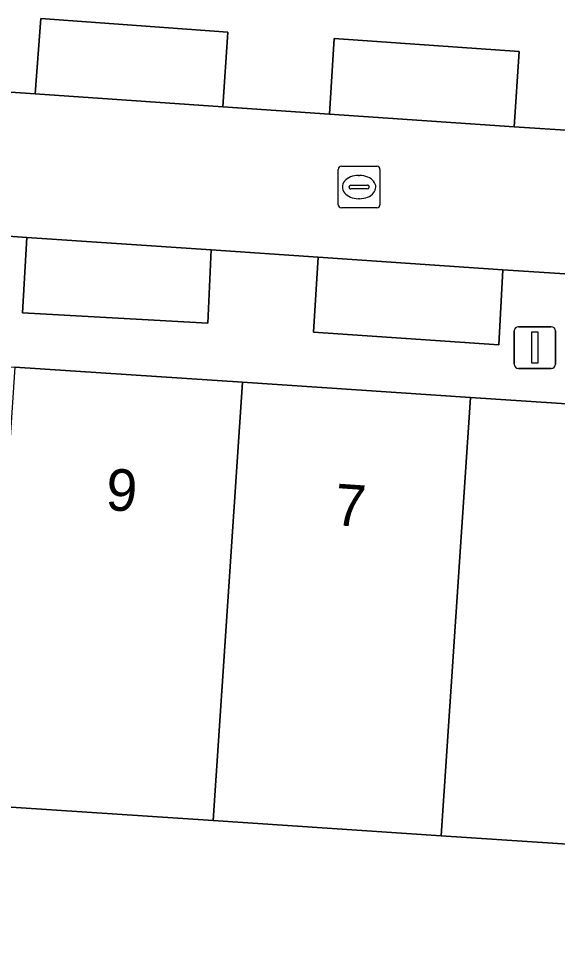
# Model space of a CAD drawing. Extents: x 159960 to 160866, y 382700 to 383354.
# Drawn here: x 160706.99 to 160719.94, y 382866.16 to 382888.46 of the extents above; entities that cross this region are included whole.
import ezdxf

# ---------------------------------------------------------------- set-up
doc = ezdxf.new("R2010")
doc.units = 0
for name, color, linetype in [('IMGEO_Erf', 7, 'Continuous'), ('IMGEO_Kolk', 7, 'Continuous'), ('IMGEO_Lichtmast', 7, 'Continuous'), ('IMGEO_Pand', 7, 'Continuous'), ('IMGEO_Pand_nummerreeks', 7, 'Continuous'), ('IMGEO_Parkeervlak_open', 7, 'Continuous'), ('IMGEO_Rijbaan_lokaal_open', 7, 'Continuous'), ('IMGEO_Voetpad_open', 7, 'Continuous')]:
    doc.layers.add(name, color=color, linetype=linetype)

msp = doc.modelspace()

# ---------------------------------------------------------------- linework, layer by layer
at = {"layer": 'IMGEO_Erf'}
msp.add_lwpolyline([(160727.919, 382864.809), (160728.103, 382868.092), (160722.617, 382868.458), (160717.143, 382868.823), (160711.667, 382869.188), (160706.193, 382869.553), (160700.717, 382869.918), (160695.243, 382870.283), (160689.627, 382870.657), (160689.38, 382863.428)], dxfattribs=at)
at = {"layer": 'IMGEO_Kolk'}
for p, q in [((160714.67, 382883.988), (160714.67, 382884.84)), ((160714.745, 382884.914), (160715.597, 382884.914)), ((160715.671, 382884.84), (160715.671, 382883.988)), ((160715.158, 382884.694), (160715.183, 382884.694)), ((160714.929, 382884.408), (160714.929, 382884.42)), ((160715.367, 382884.371), (160714.969, 382884.371)), ((160714.972, 382884.457), (160715.37, 382884.457)), ((160715.413, 382884.42), (160715.413, 382884.408)), ((160715.181, 382884.134), (160715.156, 382884.134)), ((160715.597, 382883.914), (160714.745, 382883.914))]:
    msp.add_line(p, q, dxfattribs=at)
for points in [[(160714.67, 382883.988), (160714.67, 382884.84)], [(160714.745, 382884.914), (160715.597, 382884.914)], [(160715.671, 382884.84), (160715.671, 382883.988)], [(160715.597, 382883.914), (160714.745, 382883.914)]]:
    msp.add_lwpolyline(points, dxfattribs=at)
for centre, radius, start, end in [((160714.747, 382884.838), 0.0765, 91.552, 178.448), ((160714.747, 382884.838), 0.0765, 91.552, 178.448), ((160715.595, 382884.838), 0.0765, 1.552, 88.448), ((160715.595, 382884.838), 0.0765, 1.552, 88.448), ((160714.969, 382884.417), 0.0403, 85.8775, 175.7526), ((160714.966, 382884.407), 0.0366, 178.938, 274.7102), ((160715.37, 382884.414), 0.043, 264.8664, 352.4533), ((160715.374, 382884.419), 0.0386, 1.7309, 96.639), ((160714.747, 382883.99), 0.0765, 181.552, 268.448), ((160714.747, 382883.99), 0.0765, 181.552, 268.448), ((160715.595, 382883.99), 0.0765, 271.552, 358.448), ((160715.595, 382883.99), 0.0765, 271.552, 358.448)]:
    msp.add_arc(centre, radius, start, end, dxfattribs=at)
for centre, major_axis, ratio, start_param, end_param in [((160715.157, 382884.414), (-0.387, 0.002), 0.722429, 4.712389, 7.853982), ((160715.182, 382884.414), (-0.39, 0.002), 0.717154, 1.570796, 4.712389)]:
    msp.add_ellipse(centre, major_axis=major_axis, ratio=ratio, start_param=start_param, end_param=end_param, dxfattribs=at)
at = {"layer": 'IMGEO_Lichtmast'}
for p, q in [((160718.998, 382881.057), (160719.788, 382881.057)), ((160719.788, 382881.057), (160718.998, 382881.057)), ((160718.898, 382880.157), (160718.898, 382880.957)), ((160718.898, 382880.957), (160718.898, 382880.157)), ((160719.888, 382880.957), (160719.888, 382880.157)), ((160719.888, 382880.157), (160719.888, 382880.957)), ((160719.788, 382880.057), (160718.998, 382880.057)), ((160718.998, 382880.057), (160719.788, 382880.057))]:
    msp.add_line(p, q, dxfattribs=at)
msp.add_lwpolyline([(160719.318, 382880.932), (160719.468, 382880.932), (160719.468, 382880.182), (160719.318, 382880.182), (160719.318, 382880.932)], dxfattribs=at)
for centre, start, end in [((160718.998, 382880.957), 90, 180), ((160718.998, 382880.957), 90, 180), ((160719.788, 382880.957), 0, 90), ((160719.788, 382880.957), 360, 90), ((160718.998, 382880.157), 180, 270), ((160718.998, 382880.157), 180, 270), ((160719.788, 382880.157), 270, 0), ((160719.788, 382880.157), 270, 0)]:
    msp.add_arc(centre, 0.1, start, end, dxfattribs=at)
at = {"layer": 'IMGEO_Pand'}
for points in [[(160706.895, 382880.089), (160706.193, 382869.553), (160711.667, 382869.188), (160712.37, 382879.724)], [(160712.37, 382879.724), (160711.667, 382869.188), (160717.143, 382868.823), (160717.845, 382879.359)], [(160717.845, 382879.359), (160717.143, 382868.823), (160722.617, 382868.458), (160723.32, 382878.994)]]:
    msp.add_lwpolyline(points, close=True, dxfattribs=at)
at = {"layer": 'IMGEO_Parkeervlak_open'}
for points in [[(160707.389, 382886.652), (160711.899, 382886.343), (160712.014, 382888.137), (160707.521, 382888.464)], [(160718.9, 382885.865), (160719.018, 382887.676), (160714.568, 382887.981), (160714.461, 382886.168)], [(160711.614, 382882.904), (160707.184, 382883.204), (160707.082, 382881.395), (160711.539, 382881.146)], [(160714.187, 382882.73), (160714.076, 382880.924), (160718.525, 382880.623), (160718.623, 382882.426)]]:
    msp.add_lwpolyline(points, close=True, dxfattribs=at)
at = {"layer": 'IMGEO_Rijbaan_lokaal_open'}
msp.add_lwpolyline([(160720.375, 382885.764), (160718.9, 382885.865), (160714.461, 382886.168), (160711.899, 382886.343), (160707.389, 382886.652), (160695.238, 382887.483), (160690.784, 382887.786), (160689.175, 382887.896), (160688.948, 382884.437), (160690.605, 382884.325), (160695.046, 382884.023), (160696.538, 382883.922), (160700.993, 382883.62), (160702.498, 382883.52), (160705.703, 382883.304), (160707.184, 382883.204), (160711.614, 382882.904), (160714.187, 382882.73), (160718.623, 382882.426), (160720.242, 382882.32)], dxfattribs=at)
at = {"layer": 'IMGEO_Voetpad_open'}
for points in [[(160695.238, 382887.483), (160707.389, 382886.652), (160707.521, 382888.464), (160712.014, 382888.137), (160711.899, 382886.343), (160714.461, 382886.168), (160714.568, 382887.981), (160719.018, 382887.676), (160718.9, 382885.865), (160720.375, 382885.764)], [(160720.242, 382882.32), (160718.623, 382882.426), (160718.525, 382880.623), (160714.076, 382880.924), (160714.187, 382882.73), (160711.614, 382882.904), (160711.539, 382881.146), (160707.082, 382881.395), (160707.184, 382883.204), (160705.703, 382883.304), (160705.597, 382881.492), (160702.355, 382881.735), (160702.498, 382883.52), (160700.993, 382883.62), (160700.899, 382881.835), (160696.443, 382882.132), (160696.538, 382883.922), (160695.046, 382884.023)], [(160661.83, 382883.064), (160667.318, 382882.704), (160672.806, 382882.343), (160678.294, 382881.983), (160683.783, 382881.623), (160689.421, 382881.253), (160690.319, 382881.194), (160695.945, 382880.819), (160701.42, 382880.454), (160706.895, 382880.089), (160712.37, 382879.724), (160717.845, 382879.359), (160723.32, 382878.994)]]:
    msp.add_lwpolyline(points, dxfattribs=at)

# ---------------------------------------------------------------- texts
at = {"layer": 'IMGEO_Pand_nummerreeks'}
for s, p in [('9', (160709.064, 382876.657)), ('7', (160714.561, 382876.29))]:
    msp.add_text(s, height=1, rotation=356.186, dxfattribs=at).set_placement(p)

doc.saveas('drawing.dxf')
